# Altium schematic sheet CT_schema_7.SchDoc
size 287 x 160 mm
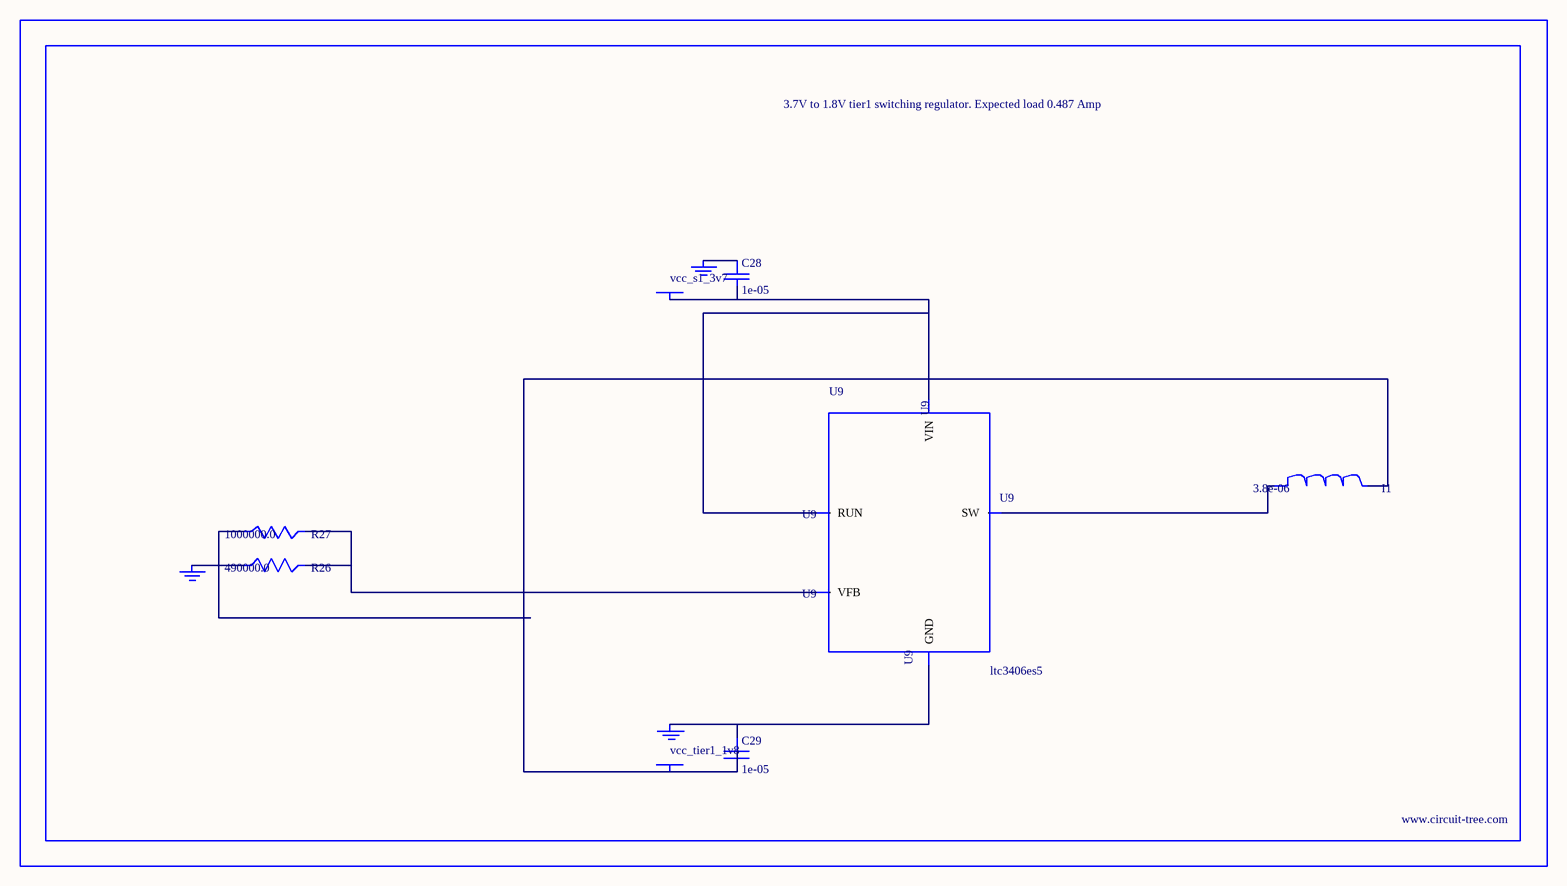
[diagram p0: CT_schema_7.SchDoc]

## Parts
BORDER6  (no value)
C28  1e-05  [C0805]
C29  1e-05  [C0805]
GND_INSTANCE_6_0  (no value)
GND_INSTANCE_6_1  (no value)
GND_INSTANCE_6_2  (no value)
I1  3.8e-06  [DR1040]
POWER_INSTANCE_6_0  vcc_tier1_1v8
POWER_INSTANCE_6_1  vcc_s1_3v7
R26  490000.0  [R0603]
R27  1000000.0  [R0603]
U9  ltc3406es5  [TSOT-23-5]

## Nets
NetC28_1: C28.1 GND_INSTANCE_6_1.0(GND)
NetC28_2: C28.2 POWER_INSTANCE_6_1.0(PWR) U9.1(RUN) U9.4(VIN)
NetC29_1: C29.1 GND_INSTANCE_6_0.0(GND) U9.2(GND)
NetC29_2: C29.2 I1.2 POWER_INSTANCE_6_0.0(PWR) R27.1
NetGND_INSTANCE_6_2_0: GND_INSTANCE_6_2.0(GND) R26.1
NetI1_1: I1.1 U9.3(SW)
NetR26_2: R26.2 R27.2 U9.5(VFB)

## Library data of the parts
BORDER6 = BORDER_PAGE6
C28 C29 = C0805C106K8RACTU
GND_INSTANCE_6_0-GND_INSTANCE_6_2 = GND
I1 = DR1040-3R8-R
POWER_INSTANCE_6_0 POWER_INSTANCE_6_1 = PWR
R26 = R26
R27 = RC0603JR-071ML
